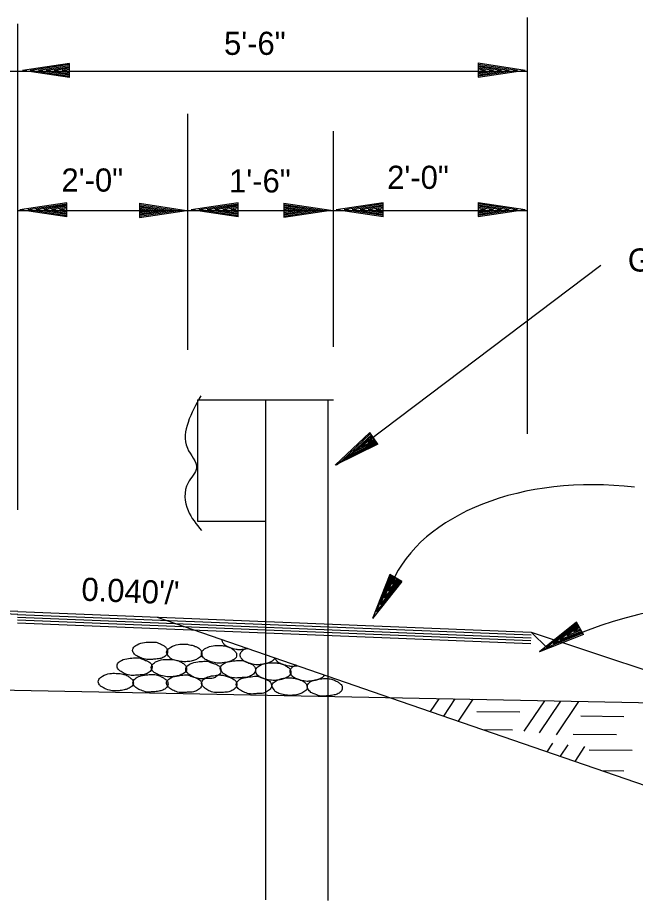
# Model space of a CAD drawing. Extents: x 1929624 to 1935547, y 596315 to 605721.
# Drawn here: x 1932958.2 to 1933120.2, y 604780.4 to 605012 of the extents above; entities that cross this region are included whole.
import ezdxf

# ---------------------------------------------------------------- set-up
doc = ezdxf.new("R2010")
doc.units = 0
doc.layers.add('Default', color=7, linetype='Continuous')
doc.layers.add('R_Annotation', color=7, linetype='Continuous')

msp = doc.modelspace()

# ---------------------------------------------------------------- linework, layer by layer
at = {"layer": 'Default'}
for p, q in [((1932958.29, 604882.92), (1932958.29, 605010.47)), ((1933091.99, 604902.81), (1933091.99, 605012.05)), ((1932971.83, 605000.04), (1932959.5, 604998.19)), ((1932971.83, 604996.32), (1932959.5, 604998.19)), ((1932971.83, 604999.72), (1932961.57, 604998.19)), ((1932971.83, 604996.64), (1932961.57, 604998.19)), ((1932971.83, 604999.4), (1932963.68, 604998.19)), ((1932971.83, 604996.96), (1932963.68, 604998.19)), ((1932971.83, 604999.1), (1932965.75, 604998.19)), ((1932971.83, 604997.25), (1932965.75, 604998.19)), ((1932971.83, 604998.78), (1932967.82, 604998.19)), ((1932971.83, 604997.57), (1932967.82, 604998.19)), ((1932971.83, 604998.46), (1932969.88, 604998.19)), ((1932971.83, 604997.89), (1932969.88, 604998.19)), ((1932971.83, 604996.32), (1932971.83, 605000.04)), ((1933079.05, 605000.16), (1933091.38, 604998.29)), ((1933079.05, 605000.16), (1933079.05, 604996.44)), ((1933079.05, 604999.84), (1933089.31, 604998.29)), ((1933079.05, 604999.52), (1933087.19, 604998.29)), ((1933079.05, 604999.22), (1933085.13, 604998.29)), ((1933079.05, 604998.9), (1933083.06, 604998.29)), ((1933079.05, 604998.58), (1933080.99, 604998.29)), ((1933079.05, 604996.44), (1933091.38, 604998.29)), ((1933079.05, 604997.7), (1933083.06, 604998.29)), ((1933079.05, 604997.08), (1933087.19, 604998.29)), ((1933079.05, 604996.76), (1933089.31, 604998.29)), ((1933079.05, 604997.38), (1933085.13, 604998.29)), ((1933079.05, 604998.02), (1933080.99, 604998.29)), ((1932761.46, 604997.97), (1933091.99, 604997.97)), ((1933002.85, 604924.9), (1933002.85, 604986.77)), ((1933041.06, 604925.71), (1933041.06, 604982.27)), ((1932971.16, 604963.47), (1932958.84, 604961.63)), ((1932971.16, 604959.76), (1932971.16, 604963.47)), ((1933016.06, 604963.47), (1933003.74, 604961.63)), ((1933016.06, 604959.76), (1933016.06, 604963.47)), ((1933054.15, 604963.5), (1933041.82, 604961.65)), ((1933054.15, 604959.78), (1933054.15, 604963.5)), ((1933079.05, 604963.57), (1933091.38, 604961.7)), ((1933079.05, 604963.57), (1933079.05, 604959.86)), ((1932958.29, 604961.41), (1933091.99, 604961.41)), ((1932971.16, 604959.76), (1932958.84, 604961.63)), ((1932971.16, 604963.15), (1932960.9, 604961.63)), ((1932971.16, 604960.08), (1932960.9, 604961.63)), ((1932971.16, 604962.83), (1932963.02, 604961.63)), ((1932971.16, 604960.4), (1932963.02, 604961.63)), ((1932971.16, 604962.54), (1932965.09, 604961.63)), ((1932971.16, 604960.69), (1932965.09, 604961.63)), ((1932971.16, 604962.22), (1932967.15, 604961.63)), ((1932971.16, 604961.01), (1932967.15, 604961.63)), ((1932971.16, 604961.9), (1932969.22, 604961.63)), ((1932971.16, 604961.33), (1932969.22, 604961.63)), ((1932990.18, 604963.35), (1933002.51, 604961.48)), ((1932990.18, 604963.35), (1932990.18, 604959.64)), ((1932990.18, 604963.03), (1933000.44, 604961.48)), ((1932990.18, 604962.71), (1932998.32, 604961.48)), ((1932990.18, 604962.42), (1932996.26, 604961.48)), ((1932990.18, 604962.1), (1932994.19, 604961.48)), ((1932990.18, 604961.78), (1932992.12, 604961.48)), ((1932990.18, 604959.64), (1933002.51, 604961.48)), ((1932990.18, 604960.89), (1932994.19, 604961.48)), ((1932990.18, 604960.28), (1932998.32, 604961.48)), ((1932990.18, 604959.96), (1933000.44, 604961.48)), ((1932990.18, 604960.57), (1932996.26, 604961.48)), ((1932990.18, 604961.21), (1932992.12, 604961.48)), ((1933016.06, 604959.76), (1933003.74, 604961.63)), ((1933016.06, 604963.15), (1933005.8, 604961.63)), ((1933016.06, 604960.08), (1933005.8, 604961.63)), ((1933016.06, 604962.83), (1933007.92, 604961.63)), ((1933016.06, 604960.4), (1933007.92, 604961.63)), ((1933016.06, 604962.54), (1933009.99, 604961.63)), ((1933016.06, 604960.69), (1933009.99, 604961.63)), ((1933016.06, 604962.22), (1933012.05, 604961.63)), ((1933016.06, 604961.01), (1933012.05, 604961.63)), ((1933016.06, 604961.9), (1933014.12, 604961.63)), ((1933016.06, 604961.33), (1933014.12, 604961.63)), ((1933028.05, 604963.38), (1933040.37, 604961.51)), ((1933028.05, 604963.38), (1933028.05, 604959.66)), ((1933028.05, 604963.06), (1933038.31, 604961.51)), ((1933028.05, 604962.74), (1933036.19, 604961.51)), ((1933028.05, 604962.44), (1933034.12, 604961.51)), ((1933028.05, 604962.12), (1933032.06, 604961.51)), ((1933028.05, 604961.8), (1933029.99, 604961.51)), ((1933028.05, 604959.66), (1933040.37, 604961.51)), ((1933028.05, 604960.92), (1933032.06, 604961.51)), ((1933028.05, 604960.3), (1933036.19, 604961.51)), ((1933028.05, 604959.98), (1933038.31, 604961.51)), ((1933028.05, 604960.6), (1933034.12, 604961.51)), ((1933028.05, 604961.23), (1933029.99, 604961.51)), ((1933054.15, 604959.78), (1933041.82, 604961.65)), ((1933054.15, 604963.18), (1933043.89, 604961.65)), ((1933054.15, 604960.1), (1933043.89, 604961.65)), ((1933054.15, 604962.86), (1933046.01, 604961.65)), ((1933054.15, 604960.42), (1933046.01, 604961.65)), ((1933054.15, 604962.56), (1933048.07, 604961.65)), ((1933054.15, 604960.72), (1933048.07, 604961.65)), ((1933054.15, 604962.24), (1933050.14, 604961.65)), ((1933054.15, 604961.04), (1933050.14, 604961.65)), ((1933054.15, 604961.92), (1933052.21, 604961.65)), ((1933054.15, 604961.36), (1933052.21, 604961.65)), ((1933079.05, 604963.25), (1933089.31, 604961.7)), ((1933079.05, 604962.93), (1933087.19, 604961.7)), ((1933079.05, 604962.64), (1933085.13, 604961.7)), ((1933079.05, 604962.32), (1933083.06, 604961.7)), ((1933079.05, 604962), (1933080.99, 604961.7)), ((1933079.05, 604959.86), (1933091.38, 604961.7)), ((1933079.05, 604961.11), (1933083.06, 604961.7)), ((1933079.05, 604960.5), (1933087.19, 604961.7)), ((1933079.05, 604960.18), (1933089.31, 604961.7)), ((1933079.05, 604960.79), (1933085.13, 604961.7)), ((1933079.05, 604961.43), (1933080.99, 604961.7)), ((1933041.87, 604894.73), (1933111.18, 604947.11)), ((1933005.41, 604911.73), (1933005.41, 604879.89)), ((1933005.41, 604911.73), (1933041.06, 604911.73)), ((1933023.25, 604911.73), (1933023.25, 604780.54)), ((1933039.63, 604911.58), (1933039.63, 604780.42)), ((1933050.62, 604903.15), (1933041.55, 604894.59)), ((1933050.81, 604902.91), (1933043.23, 604895.75)), ((1933051.01, 604902.61), (1933045.03, 604897.02)), ((1933051.13, 604902.36), (1933046.7, 604898.18)), ((1933052.17, 604900.91), (1933046.7, 604898.18)), ((1933051.32, 604902.14), (1933048.37, 604899.36)), ((1933051.97, 604901.18), (1933048.37, 604899.36)), ((1933051.49, 604901.87), (1933050.07, 604900.55)), ((1933051.85, 604901.46), (1933050.07, 604900.55)), ((1933052.71, 604900.14), (1933050.62, 604903.15)), ((1933052.71, 604900.14), (1933041.55, 604894.59)), ((1933052.56, 604900.37), (1933043.23, 604895.75)), ((1933052.34, 604900.64), (1933045.03, 604897.02)), ((1933005.41, 604879.89), (1933023.25, 604879.89)), ((1933055.85, 604865.97), (1933051.27, 604854.36)), ((1933059.05, 604864.1), (1933051.27, 604854.36)), ((1933056.09, 604865.77), (1933052.31, 604856.15)), ((1933058.8, 604864.27), (1933052.31, 604856.15)), ((1933056.39, 604865.62), (1933053.36, 604858)), ((1933058.48, 604864.39), (1933053.36, 604858)), ((1933056.64, 604865.48), (1933054.37, 604859.74)), ((1933058.23, 604864.57), (1933054.37, 604859.74)), ((1933056.93, 604865.33), (1933055.43, 604861.57)), ((1933057.96, 604864.71), (1933055.43, 604861.57)), ((1933059.05, 604864.1), (1933055.85, 604865.97)), ((1933057.23, 604865.16), (1933056.49, 604863.34)), ((1933057.69, 604864.89), (1933056.49, 604863.34)), ((1932958.29, 604856.2), (1932810.67, 604862.11)), ((1932958.29, 604855.46), (1932810.67, 604861.37)), ((1932958.23, 604854.73), (1933092.89, 604849.34)), ((1932958.25, 604855.46), (1933092.91, 604850.08)), ((1932958.29, 604856.2), (1933092.95, 604850.81)), ((1932994.82, 604854.74), (1933056.06, 604833.6)), ((1932958.17, 604853.25), (1933092.83, 604847.86)), ((1932958.2, 604853.99), (1933092.85, 604848.6)), ((1933104.81, 604853.45), (1933095.07, 604845.67)), ((1933104.98, 604853.15), (1933096.86, 604846.68)), ((1933105.13, 604852.88), (1933098.68, 604847.76)), ((1933105.28, 604852.63), (1933100.45, 604848.8)), ((1933105.42, 604852.34), (1933102.25, 604849.83)), ((1933106.68, 604850.22), (1933104.81, 604853.45)), ((1933092.95, 604850.81), (1933273.58, 604790.77)), ((1933092.95, 604850.81), (1933097.18, 604846.61)), ((1933106.68, 604850.22), (1933095.07, 604845.67)), ((1933106.51, 604850.49), (1933096.86, 604846.68)), ((1933106.34, 604850.76), (1933098.68, 604847.76)), ((1933106.19, 604851.01), (1933100.45, 604848.8)), ((1933106.04, 604851.28), (1933102.25, 604849.83)), ((1933105.6, 604852.07), (1933104.07, 604850.86)), ((1933105.89, 604851.58), (1933104.07, 604850.86)), ((1932757.02, 604839.54), (1933150.4, 604831.72)), ((1933056.06, 604833.6), (1933180.12, 604790.77))]:
    msp.add_line(p, q, dxfattribs=at)
msp.add_arc((1933150.58, 604737.34), 121.72, 64.8876, 117.1378, dxfattribs=at)
msp.add_ellipse((1933115.17, 604848.94), major_axis=(-60.8, 7.42), ratio=0.655798, start_param=4.712389, end_param=6.093533, dxfattribs=at)
for points in [[(1933006.27, 604912.77), (1933002.93, 604905.85), (1933002.75, 604899.11), (1933005.16, 604893.92), (1933002.93, 604889.98), (1933002.93, 604882.72), (1933006.47, 604877.48)], [(1932993.16, 604848.19), (1932991.53, 604848.09), (1932989.57, 604847.5), (1932988.53, 604846.57), (1932988.38, 604846.02), (1932988.88, 604845.04), (1932989.47, 604844.6), (1932990.6, 604844.06), (1932992.17, 604843.61), (1932993.01, 604843.61), (1932994.19, 604843.71), (1932995.52, 604843.86), (1932996.55, 604844.25), (1932997.44, 604845.09), (1932997.59, 604845.73), (1932997.29, 604846.61), (1932996.65, 604847.2), (1932995.96, 604847.6), (1932994.88, 604848.04), (1932994.19, 604848.19), (1932993.16, 604848.19)], [(1933001.97, 604847.66), (1933000.35, 604847.57), (1932998.43, 604846.88), (1932997.45, 604846.09), (1932997.3, 604845.55), (1932997.84, 604844.51), (1932998.28, 604843.97), (1932999.46, 604843.48), (1933000.94, 604843.14), (1933001.78, 604843.04), (1933003.01, 604843.09), (1933004.39, 604843.33), (1933005.37, 604843.78), (1933006.4, 604844.56), (1933006.55, 604845.2), (1933006.26, 604846.09), (1933005.52, 604846.73), (1933004.78, 604847.07), (1933003.7, 604847.42), (1933003.01, 604847.57), (1933001.97, 604847.66)], [(1933011.77, 604848.89), (1933011.77, 604848.85), (1933011.77, 604848.79), (1933011.78, 604848.72), (1933011.85, 604848.45), (1933011.97, 604848.19), (1933012.12, 604847.93), (1933012.22, 604847.81), (1933012.32, 604847.69), (1933012.57, 604847.44), (1933012.86, 604847.25), (1933013.12, 604847.1), (1933013.39, 604846.97), (1933013.66, 604846.85), (1933013.94, 604846.75), (1933014.72, 604846.53), (1933015.52, 604846.36), (1933015.93, 604846.29), (1933016.14, 604846.27), (1933016.35, 604846.26), (1933016.94, 604846.29), (1933017.24, 604846.32), (1933017.53, 604846.36), (1933018.05, 604846.44), (1933018.57, 604846.54)], [(1933011.15, 604847.29), (1933009.53, 604847.25), (1933007.56, 604846.56), (1933006.58, 604845.67), (1933006.43, 604845.08), (1933006.97, 604844.1), (1933007.51, 604843.65), (1933008.59, 604843.16), (1933010.17, 604842.72), (1933011, 604842.67), (1933012.18, 604842.77), (1933013.51, 604843.01), (1933014.55, 604843.41), (1933015.53, 604844.19), (1933015.68, 604844.79), (1933015.38, 604845.67), (1933014.65, 604846.26), (1933013.96, 604846.75), (1933012.87, 604847.1), (1933012.18, 604847.25), (1933011.15, 604847.29)], [(1933018.43, 604846.59), (1933018.13, 604846.47), (1933017.89, 604846.36), (1933017.65, 604846.24), (1933017.36, 604846.05), (1933017.1, 604845.84), (1933016.88, 604845.59), (1933016.77, 604845.45), (1933016.66, 604845.3), (1933016.59, 604845.17), (1933016.54, 604845.03), (1933016.51, 604844.89), (1933016.51, 604844.83), (1933016.52, 604844.76), (1933016.59, 604844.49), (1933016.71, 604844.23), (1933016.86, 604843.97), (1933016.96, 604843.85), (1933017.06, 604843.73), (1933017.31, 604843.48), (1933017.6, 604843.28), (1933017.86, 604843.14), (1933018.13, 604843.01), (1933018.4, 604842.89), (1933018.68, 604842.79), (1933019.46, 604842.57), (1933020.26, 604842.4), (1933021.09, 604842.3), (1933021.24, 604842.3), (1933021.39, 604842.31), (1933021.68, 604842.33), (1933022.27, 604842.4), (1933022.61, 604842.45), (1933022.94, 604842.51), (1933023.27, 604842.57), (1933023.6, 604842.64), (1933023.87, 604842.72), (1933024.13, 604842.81), (1933024.38, 604842.92), (1933024.64, 604843.04), (1933024.91, 604843.18), (1933025.17, 604843.35), (1933025.4, 604843.56), (1933025.51, 604843.68), (1933025.62, 604843.82), (1933025.69, 604843.94), (1933025.74, 604844.07)], [(1932989.08, 604844.08), (1932987.36, 604843.88), (1932985.44, 604843.39), (1932984.46, 604842.46), (1932984.31, 604841.91), (1932984.8, 604840.88), (1932985.39, 604840.44), (1932986.47, 604839.85), (1932988.05, 604839.45), (1932988.84, 604839.45), (1932990.07, 604839.55), (1932991.44, 604839.65), (1932992.48, 604840.14), (1932993.36, 604840.98), (1932993.51, 604841.62), (1932993.22, 604842.51), (1932992.48, 604843.1), (1932991.79, 604843.39), (1932990.71, 604843.83), (1932990.07, 604844.03), (1932989.08, 604844.08)], [(1932998.01, 604843.66), (1932996.39, 604843.61), (1932994.42, 604842.97), (1932993.44, 604842.04), (1932993.29, 604841.5), (1932993.83, 604840.46), (1932994.37, 604840.02), (1932995.45, 604839.53), (1932997.03, 604839.13), (1932997.87, 604839.04), (1932999.05, 604839.13), (1933000.38, 604839.38), (1933001.41, 604839.77), (1933002.39, 604840.56), (1933002.54, 604841.2), (1933002.25, 604842.09), (1933001.51, 604842.68), (1933000.82, 604843.12), (1932999.74, 604843.46), (1932999.05, 604843.61), (1932998.01, 604843.66)], [(1933007.11, 604843.16), (1933005.48, 604843.01), (1933003.52, 604842.47), (1933002.48, 604841.54), (1933002.34, 604841), (1933002.88, 604840.01), (1933003.42, 604839.57), (1933004.55, 604838.93), (1933006.07, 604838.59), (1933006.91, 604838.59), (1933008.09, 604838.68), (1933009.52, 604838.73), (1933010.5, 604839.22), (1933011.44, 604840.06), (1933011.59, 604840.7), (1933011.29, 604841.59), (1933010.6, 604842.18), (1933009.86, 604842.52), (1933008.83, 604842.87), (1933008.14, 604843.16), (1933007.11, 604843.16)], [(1933016.06, 604843.39), (1933014.44, 604843.19), (1933012.52, 604842.7), (1933011.54, 604841.77), (1933011.39, 604841.23), (1933011.93, 604840.19), (1933012.47, 604839.75), (1933013.55, 604839.16), (1933015.13, 604838.77), (1933015.92, 604838.77), (1933017.15, 604838.86), (1933018.48, 604838.96), (1933019.56, 604839.45), (1933020.49, 604840.29), (1933020.64, 604840.93), (1933020.35, 604841.82), (1933019.61, 604842.41), (1933018.87, 604842.7), (1933017.84, 604843.19), (1933017.1, 604843.34), (1933016.06, 604843.39)], [(1933025.69, 604844.08), (1933025.77, 604843.88), (1933025.88, 604843.68), (1933026.01, 604843.49), (1933026.16, 604843.3), (1933026.42, 604843.05), (1933026.7, 604842.86), (1933026.97, 604842.71), (1933027.23, 604842.58), (1933027.5, 604842.46), (1933027.78, 604842.37), (1933028.57, 604842.14), (1933029.36, 604841.97), (1933029.78, 604841.9), (1933029.99, 604841.88), (1933030.2, 604841.87), (1933030.79, 604841.9), (1933031.38, 604841.97), (1933031.68, 604842.02)], [(1933025.36, 604842.75), (1933023.74, 604842.7), (1933021.77, 604842.06), (1933020.79, 604841.13), (1933020.64, 604840.59), (1933021.18, 604839.55), (1933021.72, 604839.11), (1933022.81, 604838.62), (1933024.38, 604838.22), (1933025.22, 604838.13), (1933026.4, 604838.22), (1933027.73, 604838.47), (1933028.76, 604838.86), (1933029.74, 604839.65), (1933029.89, 604840.29), (1933029.6, 604841.18), (1933028.86, 604841.77), (1933028.17, 604842.21), (1933027.09, 604842.55), (1933026.4, 604842.7), (1933025.36, 604842.75)], [(1933031.26, 604842.16), (1933031, 604842.04), (1933030.87, 604841.97), (1933030.74, 604841.91), (1933030.44, 604841.72), (1933030.19, 604841.51), (1933029.96, 604841.26), (1933029.86, 604841.12), (1933029.75, 604840.97), (1933029.68, 604840.84), (1933029.62, 604840.7), (1933029.6, 604840.56), (1933029.6, 604840.49), (1933029.6, 604840.43), (1933029.68, 604840.16), (1933029.79, 604839.9), (1933029.95, 604839.64), (1933030.04, 604839.52), (1933030.14, 604839.4), (1933030.4, 604839.15), (1933030.69, 604838.95), (1933030.95, 604838.81), (1933031.22, 604838.68), (1933031.49, 604838.56), (1933031.77, 604838.46), (1933032.55, 604838.24), (1933033.34, 604838.07), (1933034.18, 604837.97), (1933034.33, 604837.97), (1933034.47, 604837.98), (1933034.77, 604838), (1933035.36, 604838.07), (1933035.7, 604838.12), (1933036.03, 604838.17), (1933036.36, 604838.24), (1933036.69, 604838.31), (1933036.96, 604838.39), (1933037.21, 604838.48), (1933037.47, 604838.59), (1933037.72, 604838.71), (1933038, 604838.85), (1933038.26, 604839.02), (1933038.49, 604839.23), (1933038.6, 604839.35), (1933038.65, 604839.42), (1933038.71, 604839.49), (1933038.75, 604839.57)], [(1932984.06, 604839.99), (1932982.44, 604839.94), (1932980.47, 604839.25), (1932979.54, 604838.36), (1932979.39, 604837.77), (1932979.88, 604836.79), (1932980.47, 604836.35), (1932981.5, 604835.85), (1932983.13, 604835.41), (1932983.92, 604835.36), (1932985.15, 604835.46), (1932986.47, 604835.71), (1932987.51, 604836.1), (1932988.44, 604836.89), (1932988.59, 604837.48), (1932988.29, 604838.36), (1932987.56, 604838.95), (1932986.87, 604839.45), (1932985.79, 604839.79), (1932985.1, 604839.94), (1932984.06, 604839.99)], [(1932993.17, 604839.7), (1932991.54, 604839.55), (1932989.57, 604838.96), (1932988.64, 604838.08), (1932988.49, 604837.49), (1932988.98, 604836.5), (1932989.48, 604836.06), (1932990.61, 604835.57), (1932992.13, 604835.08), (1932992.97, 604835.08), (1932994.2, 604835.17), (1932995.58, 604835.37), (1932996.56, 604835.71), (1932997.55, 604836.6), (1932997.69, 604837.19), (1932997.4, 604838.08), (1932996.66, 604838.67), (1932995.92, 604839.11), (1932994.89, 604839.5), (1932994.2, 604839.65), (1932993.17, 604839.7)], [(1933002.02, 604839.57), (1933000.39, 604839.37), (1932998.42, 604838.83), (1932997.44, 604837.95), (1932997.29, 604837.36), (1932997.83, 604836.37), (1932998.37, 604835.93), (1932999.46, 604835.34), (1933000.98, 604834.94), (1933001.82, 604834.94), (1933003.05, 604835.04), (1933004.38, 604835.14), (1933005.41, 604835.58), (1933006.39, 604836.47), (1933006.54, 604837.06), (1933006.25, 604837.95), (1933005.51, 604838.54), (1933004.77, 604838.88), (1933003.69, 604839.27), (1933003.05, 604839.52), (1933002.02, 604839.57)], [(1933011.27, 604839.58), (1933009.6, 604839.38), (1933007.63, 604838.84), (1933006.65, 604837.95), (1933006.5, 604837.36), (1933007.04, 604836.38), (1933007.58, 604835.94), (1933008.72, 604835.3), (1933010.24, 604834.95), (1933011.03, 604834.95), (1933012.26, 604835), (1933013.64, 604835.15), (1933014.67, 604835.59), (1933015.6, 604836.48), (1933015.75, 604837.07), (1933015.46, 604837.95), (1933014.72, 604838.54), (1933013.98, 604838.89), (1933012.95, 604839.23), (1933012.31, 604839.43), (1933011.27, 604839.58)], [(1933020.35, 604839.21), (1933018.62, 604839.01), (1933016.75, 604838.52), (1933015.72, 604837.58), (1933015.57, 604837.04), (1933016.11, 604836.01), (1933016.65, 604835.57), (1933017.79, 604834.98), (1933019.31, 604834.58), (1933020.1, 604834.58), (1933021.33, 604834.68), (1933022.76, 604834.78), (1933023.74, 604835.27), (1933024.68, 604836.11), (1933024.82, 604836.75), (1933024.53, 604837.63), (1933023.79, 604838.22), (1933023.1, 604838.52), (1933022.02, 604838.91), (1933021.38, 604839.16), (1933020.35, 604839.21)], [(1933029.62, 604838.83), (1933028, 604838.73), (1933026.08, 604838.04), (1933025.09, 604837.26), (1933024.95, 604836.72), (1933025.49, 604835.68), (1933025.93, 604835.14), (1933027.11, 604834.65), (1933028.59, 604834.3), (1933029.42, 604834.21), (1933030.65, 604834.25), (1933032.03, 604834.5), (1933033.02, 604834.94), (1933034.05, 604835.73), (1933034.2, 604836.37), (1933033.9, 604837.26), (1933033.16, 604837.9), (1933032.43, 604838.24), (1933031.34, 604838.59), (1933030.65, 604838.73), (1933029.62, 604838.83)], [(1933038.87, 604838.64), (1933037.25, 604838.49), (1933035.28, 604837.9), (1933034.34, 604837.02), (1933034.2, 604836.43), (1933034.69, 604835.44), (1933035.18, 604835), (1933036.31, 604834.51), (1933037.84, 604834.02), (1933038.67, 604834.02), (1933039.91, 604834.12), (1933041.28, 604834.31), (1933042.27, 604834.66), (1933043.25, 604835.54), (1933043.4, 604836.13), (1933043.1, 604837.02), (1933042.37, 604837.61), (1933041.63, 604838.05), (1933040.59, 604838.45), (1933039.91, 604838.59), (1933038.87, 604838.64)]]:
    msp.add_spline(points, degree=3, dxfattribs=at)
at = {"layer": 'R_Annotation'}
for p, q in [((1933066.52, 604829.99), (1933068.79, 604833.34)), ((1933070.01, 604828.78), (1933073.03, 604833.26)), ((1933073.87, 604827.45), (1933077.73, 604833.17)), ((1933091.1, 604824.81), (1933096.49, 604832.79)), ((1933095.08, 604824.34), (1933100.73, 604832.71)), ((1933099.53, 604823.88), (1933105.43, 604832.62)), ((1933078.68, 604830), (1933089.99, 604829.91)), ((1933105.93, 604828.8), (1933117.24, 604828.7)), ((1933080.26, 604825.24), (1933088.04, 604825.18)), ((1933103.98, 604824.07), (1933115.29, 604823.97)), ((1933097.09, 604819.43), (1933098.61, 604821.68)), ((1933100.58, 604818.23), (1933102.59, 604821.21)), ((1933104.44, 604816.89), (1933107.04, 604820.75)), ((1933108.16, 604819.91), (1933119.46, 604819.82)), ((1933111.41, 604814.49), (1933117.24, 604814.44))]:
    msp.add_line(p, q, dxfattribs=at)

# ---------------------------------------------------------------- texts
at = {"layer": 'Default'}
for s, rotation, p in [('5\'-6"', 360, (1933012.37, 605002.28)), ('2\'-0"', 360, (1933055.16, 604967.12)), ('2\'-0"', 360, (1932969.74, 604966.4)), ('1\'-6"', 360, (1933013.7, 604966.18)), ('GUARDRAIL (TYPE A)', 360, (1933118.27, 604945.42)), ("0.040'/'", 357.7094, (1932974.87, 604859.07))]:
    msp.add_text(s, height=6.075, rotation=rotation, dxfattribs=at).set_placement(p)

doc.saveas('drawing.dxf')
